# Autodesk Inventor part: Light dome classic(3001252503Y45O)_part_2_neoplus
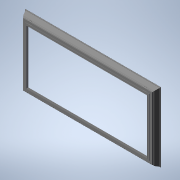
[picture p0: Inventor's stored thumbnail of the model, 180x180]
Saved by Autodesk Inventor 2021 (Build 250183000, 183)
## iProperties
Created: 2026-04
Part Number: Light dome classic(3001252503Y45O)_part_2_neoplus
Material: Generic
Catalog Web Link: www.3dfindit.com
Description: Light dome classic_part_2_neoplus-
Vendor: KINGSPAN
Document SubType Name: Modeling
Designer: psAdmin
Manufacturer: KINGSPAN
Mass: 18528.4 g
Surface Area: 36071.6 cm^2
Volume: 18528.4 cm^3
Density: 1 g/cm^3
Appearance: PSOLRGB-255-255-255
Category: PARTsolutions
Company: KINGSPAN
Title: Light dome classic(3001252503Y45O)_part_2_neoplus
Author: Cadenas PARTsolutions
PSOL_IDENT_0: {$CADENAS_DATA/23d-libs/kingspan_kla/light_dome_classic_neoplus/parts/part_2.prj},293 {VTYP=3D},{NB=
PSOL_IDENT_1: Light dome classic(3001252503Y45O)_part_2_neoplus},{LINA=Light dome classic(3001252503Y45O)_part_2_n
PSOL_IDENT_2: eoplus},{NN=Light dome classic_part_2_neoplus},{DATE=20.03.2025 09:30:52},{GEOMDATE=01.07.2024 06:23
PSOL_IDENT_3: :48},{VERSION=},{LINEID=10},{WBVAR=LODLEVEL,L,W,BA,SF,DP,OP,OC},{WBNUMERIC=W}  {NB=Light dome classi
PSOL_IDENT_4: c(3001252503Y45O)_part_2_neoplus},{LINA=Light dome classic(3001252503Y45O)_part_2_neoplus},{KT=DUMMY
PSOL_IDENT_5: },{IDNR=},{PN=Light dome classic},{LODLEVEL=300},{L=125},{W=250},{WX=125,250,300},{LX=1250},{XWX=250
PSOL_IDENT_6: 0},{BA=3},{SF=Y},{SFX='Y','Yes','N','No'},{DRIVE=1},{DPX='1', 'Natural ventilation', '2' , 'NSHEV (n
PSOL_IDENT_7: atural smoke, heat exhaust ventilation)', '3', 'Fixed','4','NSHE'},{DP=4},{OPX='5','Pneumatic - NRWG
PSOL_IDENT_8: F.6 LK'},{OP=5},{OCX='O', 'Open', 'C', 'Closed'},{OC=O}
NB: Light dome classic(3001252503Y45O)_part_2_neoplus
NN: Light dome classic_part_2_neoplus
NBSYN: $PN.($LODLEVEL.$L.$W.$BA.$SF.$DP.$OP.$OC.)_part_2_neoplus
LINA: Light dome classic(3001252503Y45O)_part_2_neoplus
CATALOG: Light + Air
PN: Light dome classic
LODLEVEL: 300
L: 125
W: 250
BA: PVC base 50 cm
SF: Yes
DP: NSHE
OP: Pneumatic - NRWG F.6 LK
OC: Open
SUPPLIER: KINGSPAN
ARTICLENO: Light dome classic(3001252503Y45O)_part_2_neoplus
BOMINFO: Light dome classic(3001252503Y45O)_part_2_neoplus
CREATOR: CADENAS GmbH
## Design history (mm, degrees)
sketch "Sketch_1"
  geometry: L1 (-1143, 334)-(-1145.2, 334); L2 (-1145.2, 334)-(-1145.2, 327); L3 (-1145.2, 327)-(-1174, 327); L4 (-1174, 327)-(-1174, 316); L5 (-1174, 316)-(-1217.8, 316); L6 (-1222, 311.8)-(-1222, 306.773); L7 (-1227, 298.113)-(-1239.32, 291); L8 (-1239.32, 291)-(-1250.849, 274.535); L9 (-1250.849, 274.535)-(-1246.754, 271.668); L10 (-1246.754, 271.668)-(-1258.226, 255.284); L11 (-1258.226, 255.284)-(-1254.129, 252.415); L12 (-1254.129, 252.415)-(-1265.6, 236.032); L13 (-1265.6, 236.032)-(-1261.507, 233.166); L14 (-1261.507, 233.166)-(-1271.208, 219.311); L15 (-1271.208, 219.311)-(-1282.773, 219.311); L16 (-1282.773, 219.311)-(-1282.773, 204.131); L17 (-1282.773, 204.131)-(-1275.173, 204.131); L18 (-1269.959, 217.26)-(-1258.443, 233.706); L19 (-1258.443, 233.706)-(-1262.536, 236.572); L20 (-1262.536, 236.572)-(-1251.065, 252.955); L21 (-1251.065, 252.955)-(-1255.162, 255.824); L22 (-1255.162, 255.824)-(-1243.69, 272.208); L23 (-1243.69, 272.208)-(-1247.785, 275.075); L24 (-1247.785, 275.075)-(-1237.798, 289.339); L25 (-1237.798, 289.339)-(-1231.456, 293); L26 (-1231.456, 293)-(-1143, 293); L27 (-1143, 293)-(-1143, 334); A1 r 4.2 centre (-1217.8, 311.8) between (-1217.8, 316) and (-1222, 311.8); A2 r 10 centre (-1232, 306.773) between (-1227, 298.113) and (-1222, 306.773); A3 r 7.6 centre (-1275.173, 211.731) between (-1275.173, 204.131) and (-1269.959, 217.26)
  constraints: 54 end point, 6 point on circle, 3 centre point
extrude "Extrusion1" join sketch "Sketch_1" stored distance "d0" = 2500; taper "d1" = 0 deg
sketch "Sketch_2"
  geometry: L1 (520.2, 334)-(518, 334); L2 (518, 334)-(518, 293); L3 (518, 293)-(606.456, 293); L4 (606.456, 293)-(612.798, 289.339); L5 (612.798, 289.339)-(622.785, 275.075); L6 (622.785, 275.075)-(618.69, 272.208); L7 (618.69, 272.208)-(630.162, 255.824); L8 (630.162, 255.824)-(626.065, 252.955); L9 (626.065, 252.955)-(637.536, 236.572); L10 (637.536, 236.572)-(633.443, 233.706); L11 (633.443, 233.706)-(644.959, 217.26); L12 (650.173, 204.131)-(657.77, 204.131); L13 (657.77, 204.131)-(657.77, 219.311); L14 (657.77, 219.311)-(646.208, 219.311); L15 (646.208, 219.311)-(636.507, 233.166); L16 (636.507, 233.166)-(640.6, 236.032); L17 (640.6, 236.032)-(629.129, 252.415); L18 (629.129, 252.415)-(633.226, 255.284); L19 (633.226, 255.284)-(621.754, 271.668); L20 (621.754, 271.668)-(625.849, 274.535); L21 (625.849, 274.535)-(614.32, 291); L22 (614.32, 291)-(602, 298.113); L23 (597, 306.773)-(597, 311.8); L24 (592.8, 316)-(549, 316); L25 (549, 316)-(549, 327); L26 (549, 327)-(520.2, 327); L27 (520.2, 327)-(520.2, 334); A1 r 7.6 centre (650.173, 211.731) between (644.959, 217.26) and (650.173, 204.131); A2 r 10 centre (607, 306.773) between (597, 306.773) and (602, 298.113); A3 r 4.2 centre (592.8, 311.8) between (597, 311.8) and (592.8, 316)
  constraints: 54 end point, 6 point on circle, 3 centre point
extrude "Extrusion2" join sketch "Sketch_2" stored distance "d2" = 5000; taper "d3" = 0 deg
sketch "Sketch_3"
  geometry: L1 (1284.773, 204.131)-(1284.773, 219.311); L2 (1284.773, 219.311)-(1271.208, 219.311); L3 (1271.208, 219.311)-(1261.507, 233.166); L4 (1261.507, 233.166)-(1265.6, 236.032); L5 (1265.6, 236.032)-(1254.129, 252.415); L6 (1254.129, 252.415)-(1258.226, 255.284); L7 (1258.226, 255.284)-(1246.754, 271.668); L8 (1246.754, 271.668)-(1250.849, 274.535); L9 (1250.849, 274.535)-(1239.32, 291); L10 (1239.32, 291)-(1227, 298.113); L11 (1222, 306.773)-(1222, 311.8); L12 (1217.8, 316)-(1174, 316); L13 (1174, 316)-(1174, 327); L14 (1174, 327)-(1145.2, 327); L15 (1145.2, 327)-(1145.2, 334); L16 (1145.2, 334)-(1143, 334); L17 (1143, 334)-(1143, 293); L18 (1143, 293)-(1231.456, 293); L19 (1231.456, 293)-(1237.798, 289.339); L20 (1237.798, 289.339)-(1247.785, 275.075); L21 (1247.785, 275.075)-(1243.69, 272.208); L22 (1243.69, 272.208)-(1255.162, 255.824); L23 (1255.162, 255.824)-(1251.065, 252.955); L24 (1251.065, 252.955)-(1262.536, 236.572); L25 (1262.536, 236.572)-(1258.443, 233.706); L26 (1258.443, 233.706)-(1269.959, 217.26); L27 (1275.173, 204.131)-(1284.773, 204.131); A1 r 10 centre (1232, 306.773) between (1222, 306.773) and (1227, 298.113); A2 r 4.2 centre (1217.8, 311.8) between (1222, 311.8) and (1217.8, 316); A3 r 7.6 centre (1275.173, 211.731) between (1269.959, 217.26) and (1275.173, 204.131)
  constraints: 54 end point, 6 point on circle, 3 centre point
extrude "Extrusion3" join sketch "Sketch_3" stored distance "d4" = 2500; taper "d5" = 0 deg
sketch "Sketch_4"
  geometry: L1 (-520.2, 334)-(-520.2, 327); L2 (-520.2, 327)-(-549, 327); L3 (-549, 327)-(-549, 316); L4 (-549, 316)-(-592.8, 316); L5 (-597, 311.8)-(-597, 306.773); L6 (-602, 298.113)-(-614.32, 291); L7 (-614.32, 291)-(-625.849, 274.535); L8 (-625.849, 274.535)-(-621.754, 271.668); L9 (-621.754, 271.668)-(-633.226, 255.284); L10 (-633.226, 255.284)-(-629.129, 252.415); L11 (-629.129, 252.415)-(-640.6, 236.032); L12 (-640.6, 236.032)-(-636.507, 233.166); L13 (-636.507, 233.166)-(-646.208, 219.311); L14 (-646.208, 219.311)-(-657.77, 219.311); L15 (-657.77, 219.311)-(-657.77, 204.131); L16 (-657.77, 204.131)-(-650.173, 204.131); L17 (-644.959, 217.26)-(-633.443, 233.706); L18 (-633.443, 233.706)-(-637.536, 236.572); L19 (-637.536, 236.572)-(-626.065, 252.955); L20 (-626.065, 252.955)-(-630.162, 255.824); L21 (-630.162, 255.824)-(-618.69, 272.208); L22 (-618.69, 272.208)-(-622.785, 275.075); L23 (-622.785, 275.075)-(-612.798, 289.339); L24 (-612.798, 289.339)-(-606.456, 293); L25 (-606.456, 293)-(-518, 293); L26 (-518, 293)-(-518, 334); L27 (-518, 334)-(-520.2, 334); A1 r 4.2 centre (-592.8, 311.8) between (-592.8, 316) and (-597, 311.8); A2 r 10 centre (-607, 306.773) between (-602, 298.113) and (-597, 306.773); A3 r 7.6 centre (-650.173, 211.731) between (-650.173, 204.131) and (-644.959, 217.26)
  constraints: 54 end point, 6 point on circle, 3 centre point
extrude "Extrusion4" join sketch "Sketch_4" stored distance "d6" = 5000; taper "d7" = 0 deg
sketch "Sketch_5"
  geometry: L1 (-1143, 357)-(-2593, 357); L2 (-2593, 357)-(-2593, -51.576); L3 (-2593, -51.576)-(-1277.437, 180.866); L4 (-1277.437, 180.866)-(-1282.657, 210.409); L5 (-1275.724, 219.311)-(-1271.208, 219.311); L6 (-1271.208, 219.311)-(-1261.507, 233.166); L7 (-1261.507, 233.166)-(-1265.6, 236.032); L8 (-1265.6, 236.032)-(-1254.129, 252.415); L9 (-1254.129, 252.415)-(-1258.226, 255.284); L10 (-1258.226, 255.284)-(-1246.754, 271.668); L11 (-1246.754, 271.668)-(-1250.849, 274.535); L12 (-1250.849, 274.535)-(-1239.32, 291); L13 (-1239.32, 291)-(-1227, 298.113); L14 (-1222, 306.773)-(-1222, 311.8); L15 (-1217.8, 316)-(-1174, 316); L16 (-1174, 316)-(-1174, 327); L17 (-1174, 327)-(-1145.2, 327); L18 (-1145.2, 327)-(-1145.2, 334); L19 (-1145.2, 334)-(-1143, 334); L20 (-1143, 334)-(-1143, 357); A1 r 7.6 centre (-1275.173, 211.731) between (-1275.724, 219.311) and (-1282.657, 210.409); A2 r 10 centre (-1232, 306.773) between (-1227, 298.113) and (-1222, 306.773); A3 r 4.2 centre (-1217.8, 311.8) between (-1217.8, 316) and (-1222, 311.8)
  constraints: 40 end point, 6 point on circle, 3 centre point
extrude "Extrusion5" cut sketch "Sketch_5" stored distance "d8" = 2500; taper "d9" = 0 deg
sketch "Sketch_6"
  geometry: L1 (2593, -51.576)-(2593, 357); L2 (2593, 357)-(1143, 357); L3 (1143, 357)-(1143, 334); L4 (1143, 334)-(1145.2, 334); L5 (1145.2, 334)-(1145.2, 327); L6 (1145.2, 327)-(1174, 327); L7 (1174, 327)-(1174, 316); L8 (1174, 316)-(1217.8, 316); L9 (1222, 311.8)-(1222, 306.773); L10 (1227, 298.113)-(1239.32, 291); L11 (1239.32, 291)-(1250.849, 274.535); L12 (1250.849, 274.535)-(1246.754, 271.668); L13 (1246.754, 271.668)-(1258.226, 255.284); L14 (1258.226, 255.284)-(1254.129, 252.415); L15 (1254.129, 252.415)-(1265.6, 236.032); L16 (1265.6, 236.032)-(1261.507, 233.166); L17 (1261.507, 233.166)-(1271.208, 219.311); L18 (1271.208, 219.311)-(1275.724, 219.311); L19 (1282.657, 210.409)-(1277.437, 180.866); L20 (1277.437, 180.866)-(2593, -51.576); A1 r 4.2 centre (1217.8, 311.8) between (1222, 311.8) and (1217.8, 316); A2 r 10 centre (1232, 306.773) between (1222, 306.773) and (1227, 298.113); A3 r 7.6 centre (1275.173, 211.731) between (1282.657, 210.409) and (1275.724, 219.311)
  constraints: 40 end point, 6 point on circle, 3 centre point
extrude "Extrusion6" cut sketch "Sketch_6" stored distance "d10" = 5000; taper "d11" = 0 deg
sketch "Sketch_7"
  geometry: L1 (518, 357)-(518, 334); L2 (518, 334)-(520.2, 334); L3 (520.2, 334)-(520.2, 327); L4 (520.2, 327)-(549, 327); L5 (549, 327)-(549, 316); L6 (549, 316)-(592.8, 316); L7 (597, 311.8)-(597, 306.773); L8 (602, 298.113)-(614.32, 291); L9 (614.32, 291)-(625.849, 274.535); L10 (625.849, 274.535)-(621.754, 271.668); L11 (621.754, 271.668)-(633.226, 255.284); L12 (633.226, 255.284)-(629.129, 252.415); L13 (629.129, 252.415)-(640.6, 236.032); L14 (640.6, 236.032)-(636.507, 233.166); L15 (636.507, 233.166)-(646.208, 219.311); L16 (646.208, 219.311)-(650.724, 219.311); L17 (657.657, 210.409)-(648.957, 161.171); L18 (648.957, 161.171)-(1343, 38.543); L19 (1343, 38.543)-(1343, 357); L20 (1343, 357)-(518, 357); A1 r 4.2 centre (592.8, 311.8) between (597, 311.8) and (592.8, 316); A2 r 10 centre (607, 306.773) between (597, 306.773) and (602, 298.113); A3 r 7.6 centre (650.173, 211.731) between (657.657, 210.409) and (650.724, 219.311)
  constraints: 40 end point, 6 point on circle, 3 centre point
extrude "Extrusion7" cut sketch "Sketch_7" stored distance "d12" = 5000; taper "d13" = 0 deg
sketch "Sketch_8"
  geometry: L1 (-518, 357)-(-1343, 357); L2 (-1343, 357)-(-1343, 38.543); L3 (-1343, 38.543)-(-648.957, 161.171); L4 (-648.957, 161.171)-(-657.657, 210.409); L5 (-650.724, 219.311)-(-646.208, 219.311); L6 (-646.208, 219.311)-(-636.507, 233.166); L7 (-636.507, 233.166)-(-640.6, 236.032); L8 (-640.6, 236.032)-(-629.129, 252.415); L9 (-629.129, 252.415)-(-633.226, 255.284); L10 (-633.226, 255.284)-(-621.754, 271.668); L11 (-621.754, 271.668)-(-625.849, 274.535); L12 (-625.849, 274.535)-(-614.32, 291); L13 (-614.32, 291)-(-602, 298.113); L14 (-597, 306.773)-(-597, 311.8); L15 (-592.8, 316)-(-549, 316); L16 (-549, 316)-(-549, 327); L17 (-549, 327)-(-520.2, 327); L18 (-520.2, 327)-(-520.2, 334); L19 (-520.2, 334)-(-518, 334); L20 (-518, 334)-(-518, 357); A1 r 7.6 centre (-650.173, 211.731) between (-650.724, 219.311) and (-657.657, 210.409); A2 r 10 centre (-607, 306.773) between (-602, 298.113) and (-597, 306.773); A3 r 4.2 centre (-592.8, 311.8) between (-592.8, 316) and (-597, 311.8)
  constraints: 40 end point, 6 point on circle, 3 centre point
extrude "Extrusion8" cut sketch "Sketch_8" stored distance "d14" = 5000; taper "d15" = 0 deg
sketch "Sketch_13"
  geometry: L1 (-319.461, 550.103)-(-318, 550); L2 (-318, 550)-(-316, 550); L3 (-316, 550)-(-316, 599.531); L4 (-316, 599.531)-(-303.205, 609.473); L5 (-308.009, 608.974)-(-307.436, 610.954); L6 (-304.441, 611.046)-(-318, 600.51); L7 (-318, 600.51)-(-318, 554); L8 (-318, 554)-(-319.461, 550.103); A1 r 4.5 centre (-306, 613) between (-303.205, 609.473) and (-308.009, 608.974); A2 r 2.5 centre (-306, 613) between (-304.441, 611.046) and (-307.436, 610.954)
  constraints: 16 end point, 4 point on circle, 2 centre point
extrude "Extrusion9" join sketch "Sketch_13" distance "d16" = 70; taper "d17" = 0 deg
sketch "Sketch_14"
  geometry: L1 (-319.461, 550.103)-(-318, 550); L2 (-318, 550)-(-316, 550); L3 (-316, 550)-(-316, 599.531); L4 (-316, 599.531)-(-303.205, 609.473); L5 (-308.009, 608.974)-(-307.436, 610.954); L6 (-304.441, 611.046)-(-318, 600.51); L7 (-318, 600.51)-(-318, 554); L8 (-318, 554)-(-319.461, 550.103); A1 r 4.5 centre (-306, 613) between (-303.205, 609.473) and (-308.009, 608.974); A2 r 2.5 centre (-306, 613) between (-304.441, 611.046) and (-307.436, 610.954)
  constraints: 16 end point, 4 point on circle, 2 centre point
extrude "Extrusion10" join sketch "Sketch_14" distance "d18" = 70; taper "d19" = 0 deg
sketch "Sketch_15"
  geometry: L1 (1049, 627.5)-(1049, 606.42); L2 (1049, 606.42)-(1067.5, 606.42); L3 (1067.5, 606.42)-(1067.5, 617.5); L4 (1067.5, 617.5)-(1100.5, 617.5); L5 (1100.5, 617.5)-(1100.5, 606.42); L6 (1100.5, 606.42)-(1119, 606.42); L7 (1119, 606.42)-(1119, 627.5); L8 (1119, 627.5)-(1049, 627.5)
  constraints: 16 end point
extrude "Extrusion11" cut sketch "Sketch_15" distance "d20" = 20; taper "d21" = 0 deg
sketch "Sketch_16"
  geometry: L1 (-1119, 606.42)-(-1100.5, 606.42); L2 (-1100.5, 606.42)-(-1100.5, 617.5); L3 (-1100.5, 617.5)-(-1067.5, 617.5); L4 (-1067.5, 617.5)-(-1067.5, 606.42); L5 (-1067.5, 606.42)-(-1049, 606.42); L6 (-1049, 606.42)-(-1049, 627.5); L7 (-1049, 627.5)-(-1119, 627.5); L8 (-1119, 627.5)-(-1119, 606.42)
  constraints: 16 end point
extrude "Extrusion12" cut sketch "Sketch_16" distance "d22" = 20; taper "d23" = 0 deg
sketch "Sketch_21"
  geometry: L1 (-1271.208, 224.311)-(-1305.173, 224.311); L2 (-1305.173, 224.311)-(-1305.173, 189.311); L3 (-1305.173, 189.311)-(-1275.173, 189.311); L4 (-1275.173, 189.311)-(-1275.173, 204.131); L5 (-1275.724, 219.311)-(-1271.208, 219.311); L6 (-1271.208, 219.311)-(-1271.208, 224.311); A1 r 7.6 centre (-1275.173, 211.731) between (-1275.724, 219.311) and (-1275.173, 204.131)
  constraints: 12 end point, 2 point on circle, 1 centre point
extrude "Extrusion13" cut sketch "Sketch_21" stored distance "d24" = 5000; taper "d25" = 0 deg
sketch "Sketch_22"
  geometry: L1 (1305.173, 224.311)-(1271.208, 224.311); L2 (1271.208, 224.311)-(1271.208, 219.311); L3 (1271.208, 219.311)-(1275.724, 219.311); L4 (1275.173, 204.131)-(1275.173, 189.311); L5 (1275.173, 189.311)-(1305.173, 189.311); L6 (1305.173, 189.311)-(1305.173, 224.311); A1 r 7.6 centre (1275.173, 211.731) between (1275.173, 204.131) and (1275.724, 219.311)
  constraints: 12 end point, 2 point on circle, 1 centre point
extrude "Extrusion14" cut sketch "Sketch_22" stored distance "d26" = 5000; taper "d27" = 0 deg
sketch "Sketch_23"
  geometry: L1 (646.208, 224.311)-(646.208, 219.311); L2 (646.208, 219.311)-(650.724, 219.311); L3 (650.173, 204.131)-(650.173, 189.311); L4 (650.173, 189.311)-(667.77, 189.311); L5 (667.77, 189.311)-(667.77, 224.311); L6 (667.77, 224.311)-(646.208, 224.311); A1 r 7.6 centre (650.173, 211.731) between (650.173, 204.131) and (650.724, 219.311)
  constraints: 12 end point, 2 point on circle, 1 centre point
extrude "Extrusion15" cut sketch "Sketch_23" stored distance "d28" = 5000; taper "d29" = 0 deg
sketch "Sketch_24"
  geometry: L1 (-646.208, 224.311)-(-667.77, 224.311); L2 (-667.77, 224.311)-(-667.77, 189.311); L3 (-667.77, 189.311)-(-650.173, 189.311); L4 (-650.173, 189.311)-(-650.173, 204.131); L5 (-650.724, 219.311)-(-646.208, 219.311); L6 (-646.208, 219.311)-(-646.208, 224.311); A1 r 7.6 centre (-650.173, 211.731) between (-650.724, 219.311) and (-650.173, 204.131)
  constraints: 12 end point, 2 point on circle, 1 centre point
extrude "Extrusion16" cut sketch "Sketch_24" stored distance "d30" = 5000; taper "d31" = 0 deg
node "IP_2_XY"
node "IP_2_YZ"
node "IP_2_ZX"
node "IP_2_X"
node "IP_2_Y"
node "IP_2_Z"
node "IP_2_Center"
node "IP_for_part_3_XY"
node "IP_for_part_3_YZ"
node "IP_for_part_3_ZX"
node "IP_for_part_3_X"
node "IP_for_part_3_Y"
node "IP_for_part_3_Z"
node "IP_for_part_3_Center"
node "IP_for_part_8_1_XY"
node "IP_for_part_8_1_YZ"
node "IP_for_part_8_1_ZX"
node "IP_for_part_8_1_X"
node "IP_for_part_8_1_Y"
node "IP_for_part_8_1_Z"
node "IP_for_part_8_1_Center"
node "IP_for_part_8_2_XY"
node "IP_for_part_8_2_YZ"
node "IP_for_part_8_2_ZX"
node "IP_for_part_8_2_X"
node "IP_for_part_8_2_Y"
node "IP_for_part_8_2_Z"
node "IP_for_part_8_2_Center"
node "IP_for_part_8_3_XY"
node "IP_for_part_8_3_YZ"
node "IP_for_part_8_3_ZX"
node "IP_for_part_8_3_X"
node "IP_for_part_8_3_Y"
node "IP_for_part_8_3_Z"
node "IP_for_part_8_3_Center"
node "IP_for_part_8_4_XY"
node "IP_for_part_8_4_YZ"
node "IP_for_part_8_4_ZX"
node "IP_for_part_8_4_X"
node "IP_for_part_8_4_Y"
node "IP_for_part_8_4_Z"
node "IP_for_part_8_4_Center"
node "IP_for_part_8_5_XY"
node "IP_for_part_8_5_YZ"
node "IP_for_part_8_5_ZX"
node "IP_for_part_8_5_X"
node "IP_for_part_8_5_Y"
node "IP_for_part_8_5_Z"
node "IP_for_part_8_5_Center"
node "IP_for_part_9_XY"
node "IP_for_part_9_YZ"
node "IP_for_part_9_ZX"
node "IP_for_part_9_X"
node "IP_for_part_9_Y"
node "IP_for_part_9_Z"
node "IP_for_part_9_Center"
body "Solid1"
other parameters: "d32" = 0
